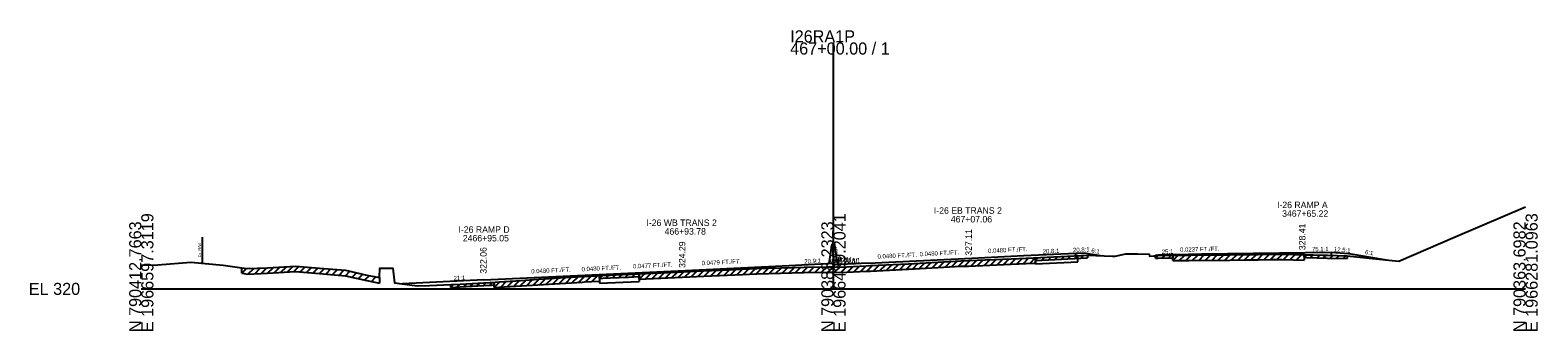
# Model space of a CAD drawing. Extents: x -44 to 4323, y -10 to 9601.
# Drawn here: x 3974.3 to 4322.8, y 5490.3 to 5559.8 of the extents above; entities that cross this region are included whole.
import ezdxf

# ---------------------------------------------------------------- set-up
doc = ezdxf.new("R2010")
doc.units = 0
for name, color, linetype in [('1', 7, 'Continuous'), ('DateStamp', 7, 'Continuous'), ('NotForConst', 7, 'Continuous'), ('QCQA', 7, 'Continuous'), ('RD_SHT_Bndy', 7, 'Continuous'), ('RD_SHT_Iplotshp', 7, 'Continuous'), ('RD_SHT_TX', 7, 'Continuous'), ('RD_XS_ExGround', 7, 'Continuous'), ('RD_XS_MedBWall', 7, 'Continuous'), ('RD_XS_Misc_Line', 7, 'Continuous'), ('RD_XS_Pave', 7, 'Continuous'), ('RD_XS_PaveOvlay', 7, 'Continuous'), ('RD_XS_PaveShd', 7, 'Continuous'), ('RD_XS_TX_Elev_PR', 7, 'Continuous'), ('RD_XS_TX_Profile', 7, 'Continuous'), ('RD_XS_TX_ShdSlope', 7, 'Continuous'), ('RD_XS_TX_Slope', 7, 'Continuous'), ('seal', 7, 'Continuous'), ('TR SN EXTRUDED PANEL SIGNS - GROUND MOUNTED', 7, 'Continuous')]:
    doc.layers.add(name, color=color, linetype=linetype)

msp = doc.modelspace()

# ---------------------------------------------------------------- linework, layer by layer
at = {"layer": 'DateStamp'}
msp.add_lwpolyline([(4000, 5505.47), (4003.81, 5505.6), (4011.45, 5506.18), (4018.89, 5505.45), (4023.21, 5504.85), (4023.8, 5504.83), (4024.5, 5504.69), (4029.18, 5504.89), (4035.64, 5505.24), (4041.22, 5504.83), (4047.17, 5504.3), (4052.17, 5503.21), (4055.03, 5502.6), (4055.14, 5504.79), (4056.24, 5504.79), (4058.14, 5504.79), (4058.5, 5501.43), (4063.27, 5500.78), (4063.83, 5500.68), (4066.62, 5500.79), (4071.55, 5500.98), (4073.68, 5501.11), (4080.54, 5501.49), (4080.98, 5501.51), (4082.67, 5501.63), (4086.58, 5501.89), (4093, 5502.3), (4101.98, 5502.84), (4102.47, 5502.87), (4106.72, 5503.1), (4108.39, 5503.18), (4112.59, 5503.38), (4115.05, 5503.49), (4118.43, 5503.64), (4130.06, 5504.16), (4138.96, 5504.58), (4142.28, 5504.73), (4153.23, 5505.02), (4158.57, 5505.13), (4160, 5505.09), (4161.33, 5505.04), (4163.09, 5505.12), (4167.58, 5505.32), (4168.59, 5505.37), (4177.35, 5505.79), (4186.84, 5506.32), (4189.47, 5506.47), (4191.22, 5506.54), (4201.11, 5506.95), (4206.35, 5507.2), (4218.7, 5507.8), (4224.5, 5507.57), (4225.14, 5507.53), (4227.61, 5508.11), (4230.33, 5508.09), (4232.97, 5508.03), (4233.07, 5507.58), (4234.13, 5507.67), (4234.44, 5507.7), (4235.06, 5507.71), (4238.44, 5507.79), (4242.25, 5507.82), (4251.6, 5507.88), (4255.59, 5507.93), (4258.18, 5507.97), (4261.19, 5508.02), (4263.67, 5508.05), (4266.35, 5507.98), (4269.33, 5507.91), (4274.21, 5507.77), (4278.79, 5507.64), (4283.86, 5507.14), (4290.68, 5506.42), (4303.75, 5512.04), (4320, 5518.99)], dxfattribs=at)
at = {"layer": 'NotForConst'}
for p, q in [((4197.85, 5505.56), (4199.15, 5506.87)), ((4199.35, 5505.63), (4200.66, 5506.93)), ((4200.85, 5505.69), (4202.17, 5507)), ((4202.36, 5505.76), (4203.68, 5507.07)), ((4203.86, 5505.83), (4205.18, 5507.15)), ((4205.37, 5505.9), (4206.69, 5507.22)), ((4206.7, 5506.59), (4207.36, 5507.25)), ((4208.21, 5506.67), (4208.86, 5507.32)), ((4209.71, 5506.74), (4210.37, 5507.4)), ((4211.21, 5506.81), (4211.87, 5507.47)), ((4212.72, 5506.88), (4213.38, 5507.54)), ((4214.22, 5506.96), (4214.88, 5507.61)), ((4215.73, 5507.03), (4216.39, 5507.69)), ((4217.23, 5507.1), (4217.89, 5507.76)), ((4234.44, 5507.07), (4235.08, 5507.71)), ((4235.95, 5507.1), (4236.59, 5507.74)), ((4237.45, 5507.14), (4238.09, 5507.78)), ((4238.44, 5506.54), (4239.7, 5507.8)), ((4239.95, 5506.55), (4241.21, 5507.81)), ((4241.45, 5506.56), (4242.71, 5507.82)), ((4242.96, 5506.57), (4244.22, 5507.83)), ((4244.46, 5506.58), (4245.72, 5507.84)), ((4245.97, 5506.59), (4247.23, 5507.85)), ((4247.47, 5506.6), (4248.73, 5507.86)), ((4248.97, 5506.61), (4250.24, 5507.87)), ((4250.48, 5506.62), (4251.74, 5507.88)), ((4251.98, 5506.63), (4253.26, 5507.9)), ((4253.49, 5506.65), (4254.76, 5507.92)), ((4254.99, 5506.68), (4256.27, 5507.94)), ((4256.5, 5506.7), (4257.77, 5507.97)), ((4258, 5506.72), (4259.28, 5507.99)), ((4259.51, 5506.74), (4260.78, 5508.01)), ((4261.01, 5506.76), (4262.28, 5508.03)), ((4262.52, 5506.78), (4263.78, 5508.05)), ((4264.02, 5506.79), (4265.25, 5508.01)), ((4265.53, 5506.75), (4266.75, 5507.97)), ((4267.03, 5506.72), (4268.26, 5507.94)), ((4268.79, 5507.3), (4269.4, 5507.91)), ((4270.29, 5507.26), (4270.9, 5507.86)), ((4271.79, 5507.21), (4272.4, 5507.82)), ((4273.3, 5507.17), (4273.91, 5507.78)), ((4274.8, 5507.13), (4275.41, 5507.73)), ((4276.31, 5507.08), (4276.92, 5507.69)), ((4277.81, 5507.04), (4278.42, 5507.65)), ((4023.21, 5503.6), (4024.33, 5504.72)), ((4024.71, 5503.45), (4026.01, 5504.75)), ((4026.21, 5503.51), (4027.51, 5504.82)), ((4027.71, 5503.58), (4029.01, 5504.89)), ((4029.21, 5503.65), (4030.53, 5504.97)), ((4030.71, 5503.73), (4032.03, 5505.05)), ((4032.21, 5503.81), (4033.53, 5505.13)), ((4033.71, 5503.89), (4035.03, 5505.21)), ((4035.21, 5503.97), (4036.42, 5505.18)), ((4036.71, 5503.91), (4037.87, 5505.08)), ((4038.21, 5503.8), (4039.37, 5504.97)), ((4039.71, 5503.69), (4040.87, 5504.86)), ((4041.21, 5503.58), (4042.35, 5504.73)), ((4042.71, 5503.45), (4043.85, 5504.6)), ((4044.21, 5503.31), (4045.35, 5504.46)), ((4045.71, 5503.18), (4046.85, 5504.32)), ((4047.21, 5503.04), (4048.23, 5504.06)), ((4048.71, 5502.71), (4049.73, 5503.74)), ((4050.21, 5502.39), (4051.23, 5503.41)), ((4111.94, 5502.72), (4112.6, 5503.38)), ((4113.44, 5502.79), (4114.1, 5503.44)), ((4115.08, 5502.24), (4116.39, 5503.55)), ((4116.58, 5502.31), (4117.9, 5503.61)), ((4118.09, 5502.37), (4119.4, 5503.68)), ((4119.59, 5502.44), (4120.91, 5503.75)), ((4121.1, 5502.51), (4122.41, 5503.82)), ((4122.6, 5502.58), (4123.92, 5503.89)), ((4124.11, 5502.64), (4125.42, 5503.95)), ((4125.61, 5502.71), (4126.93, 5504.02)), ((4127.12, 5502.78), (4128.43, 5504.09)), ((4128.62, 5502.85), (4129.94, 5504.16)), ((4130.13, 5502.92), (4131.44, 5504.23)), ((4131.63, 5502.99), (4132.95, 5504.3)), ((4133.14, 5503.06), (4134.45, 5504.37)), ((4134.64, 5503.13), (4135.96, 5504.44)), ((4136.15, 5503.2), (4137.46, 5504.51)), ((4137.65, 5503.27), (4138.97, 5504.58)), ((4139.16, 5503.34), (4140.47, 5504.65)), ((4140.66, 5503.41), (4141.98, 5504.72)), ((4142.17, 5503.48), (4143.46, 5504.76)), ((4143.67, 5503.52), (4144.96, 5504.8)), ((4145.18, 5503.56), (4146.46, 5504.84)), ((4146.68, 5503.6), (4147.97, 5504.88)), ((4148.18, 5503.63), (4149.47, 5504.92)), ((4149.69, 5503.67), (4150.98, 5504.96)), ((4151.19, 5503.71), (4152.48, 5505)), ((4152.7, 5503.75), (4153.98, 5505.03)), ((4154.2, 5503.79), (4155.49, 5505.06)), ((4155.71, 5503.82), (4156.99, 5505.1)), ((4157.21, 5503.85), (4158.5, 5505.13)), ((4158.72, 5503.87), (4159.94, 5505.09)), ((4160.22, 5503.83), (4161.45, 5505.05)), ((4161.73, 5503.81), (4163.04, 5505.12)), ((4163.23, 5503.88), (4164.55, 5505.19)), ((4164.74, 5503.95), (4166.05, 5505.25)), ((4166.24, 5504.01), (4167.56, 5505.32)), ((4167.75, 5504.08), (4169.07, 5505.39)), ((4169.25, 5504.15), (4170.57, 5505.47)), ((4170.76, 5504.22), (4172.08, 5505.54)), ((4172.26, 5504.3), (4173.58, 5505.61)), ((4173.77, 5504.37), (4175.09, 5505.68)), ((4175.27, 5504.44), (4176.59, 5505.76)), ((4176.78, 5504.52), (4178.1, 5505.83)), ((4178.28, 5504.59), (4179.61, 5505.92)), ((4179.79, 5504.68), (4181.11, 5506)), ((4181.29, 5504.76), (4182.62, 5506.09)), ((4182.8, 5504.85), (4184.12, 5506.17)), ((4184.3, 5504.93), (4185.63, 5506.25)), ((4185.81, 5505.01), (4187.13, 5506.34)), ((4187.31, 5505.1), (4188.64, 5506.42)), ((4188.82, 5505.18), (4190.14, 5506.5)), ((4190.32, 5505.25), (4191.63, 5506.56)), ((4191.83, 5505.32), (4193.13, 5506.62)), ((4193.33, 5505.38), (4194.64, 5506.68)), ((4194.84, 5505.44), (4196.14, 5506.75)), ((4196.34, 5505.5), (4197.65, 5506.81)), ((4051.71, 5502.06), (4052.74, 5503.09)), ((4053.21, 5501.74), (4054.24, 5502.77)), ((4071.55, 5500.36), (4072.21, 5501.02)), ((4073.05, 5500.44), (4073.72, 5501.11)), ((4074.56, 5500.53), (4075.22, 5501.19)), ((4076.06, 5500.62), (4076.73, 5501.28)), ((4077.57, 5500.7), (4078.23, 5501.36)), ((4079.07, 5500.79), (4079.74, 5501.45)), ((4080.58, 5500.87), (4081.24, 5501.53)), ((4081.58, 5500.3), (4082.92, 5501.65)), ((4083.08, 5500.41), (4084.43, 5501.75)), ((4084.59, 5500.51), (4085.93, 5501.85)), ((4086.09, 5500.61), (4087.44, 5501.94)), ((4087.6, 5500.71), (4088.94, 5502.04)), ((4089.1, 5500.8), (4090.44, 5502.14)), ((4090.61, 5500.9), (4091.95, 5502.24)), ((4092.11, 5501), (4093.45, 5502.33)), ((4093.62, 5501.09), (4094.95, 5502.42)), ((4095.12, 5501.18), (4096.46, 5502.51)), ((4096.63, 5501.27), (4097.96, 5502.6)), ((4098.13, 5501.36), (4099.47, 5502.69)), ((4099.64, 5501.45), (4100.97, 5502.78)), ((4101.14, 5501.54), (4102.47, 5502.87)), ((4102.65, 5501.63), (4103.97, 5502.95)), ((4104.15, 5501.71), (4105.48, 5503.03)), ((4105.92, 5502.43), (4106.58, 5503.09)), ((4107.42, 5502.51), (4108.08, 5503.16)), ((4108.93, 5502.58), (4109.59, 5503.23)), ((4110.43, 5502.65), (4111.09, 5503.3))]:
    msp.add_line(p, q, dxfattribs=at)
at = {"layer": 'QCQA'}
for p, q in [((4191.22, 5506.54), (4201.11, 5506.95)), ((4201.11, 5506.95), (4206.35, 5507.2)), ((4206.35, 5507.2), (4206.7, 5507.22)), ((4238.44, 5507.79), (4234.98, 5507.71)), ((4238.44, 5507.79), (4242.25, 5507.82)), ((4238.44, 5507.79), (4238.44, 5507.76)), ((4242.25, 5507.82), (4251.6, 5507.88)), ((4251.6, 5507.88), (4255.59, 5507.93)), ((4255.59, 5507.93), (4258.18, 5507.97)), ((4258.18, 5507.97), (4261.19, 5508.02)), ((4261.19, 5508.02), (4263.67, 5508.05)), ((4263.67, 5508.05), (4266.35, 5507.98)), ((4266.35, 5507.98), (4268.79, 5507.92)), ((4268.79, 5507.92), (4275.13, 5507.74)), ((4105.92, 5503.06), (4115.08, 5503.49)), ((4115.08, 5503.49), (4118.43, 5503.64)), ((4115.08, 5503.49), (4115.08, 5501.74)), ((4118.43, 5503.64), (4130.06, 5504.16)), ((4130.06, 5504.16), (4138.96, 5504.58)), ((4138.96, 5504.58), (4142.28, 5504.73)), ((4142.28, 5504.73), (4153.23, 5505.02)), ((4153.23, 5505.02), (4158.57, 5505.13)), ((4158.57, 5505.13), (4160, 5505.09)), ((4160, 5505.09), (4161.33, 5505.04)), ((4161.33, 5505.04), (4163.09, 5505.12)), ((4163.09, 5505.12), (4167.58, 5505.32)), ((4167.58, 5505.32), (4168.59, 5505.37)), ((4168.59, 5505.37), (4177.35, 5505.79)), ((4177.35, 5505.79), (4186.84, 5506.32)), ((4186.84, 5506.32), (4189.47, 5506.47)), ((4189.47, 5506.47), (4191.22, 5506.54)), ((4105.92, 5503.06), (4105.92, 5501.3))]:
    msp.add_line(p, q, dxfattribs=at)
at = {"layer": 'RD_SHT_Bndy'}
for p, q in [((4160, 5500), (4160, 5556.96)), ((4000, 5500), (4160, 5500)), ((4160, 5500), (4320, 5500))]:
    msp.add_line(p, q, dxfattribs=at)
at = {"layer": 'RD_SHT_Iplotshp'}
for p, q in [((4206.7, 5507.22), (4206.7, 5505.97)), ((4206.7, 5506.59), (4206.7, 5507.22)), ((4206.7, 5506.59), (4218.7, 5507.17)), ((4218.7, 5507.8), (4218.7, 5507.17)), ((4234.44, 5507.07), (4234.44, 5507.7)), ((4234.44, 5507.07), (4235.06, 5507.08)), ((4235.06, 5507.08), (4238.44, 5507.16)), ((4238.44, 5506.54), (4238.44, 5507.79)), ((4238.44, 5507.79), (4238.44, 5507.16)), ((4238.44, 5507.16), (4238.44, 5507.16)), ((4268.79, 5507.92), (4268.79, 5506.67)), ((4268.79, 5507.3), (4268.79, 5507.92)), ((4268.79, 5507.3), (4269.33, 5507.29)), ((4269.33, 5507.29), (4274.21, 5507.14)), ((4274.21, 5507.14), (4278.79, 5507.02)), ((4278.79, 5507.64), (4278.79, 5507.02)), ((4023.21, 5503.6), (4023.21, 5504.85)), ((4023.21, 5503.6), (4023.8, 5503.58)), ((4023.8, 5503.58), (4024.5, 5503.44)), ((4024.5, 5503.44), (4029.18, 5503.64)), ((4029.18, 5503.64), (4035.64, 5503.99)), ((4035.64, 5503.99), (4041.22, 5503.58)), ((4041.22, 5503.58), (4047.17, 5503.05)), ((4115.08, 5502.24), (4115.08, 5503.49)), ((4115.08, 5503.49), (4115.08, 5502.86)), ((4138.96, 5503.33), (4142.28, 5503.48)), ((4142.28, 5503.48), (4153.23, 5503.77)), ((4153.23, 5503.77), (4158.57, 5503.88)), ((4158.57, 5503.88), (4160, 5503.84)), ((4160, 5503.84), (4161.33, 5503.79)), ((4161.33, 5503.79), (4163.09, 5503.87)), ((4163.09, 5503.87), (4167.58, 5504.07)), ((4167.58, 5504.07), (4168.59, 5504.12)), ((4168.59, 5504.12), (4177.35, 5504.54)), ((4177.35, 5504.54), (4186.84, 5505.07)), ((4186.84, 5505.07), (4189.47, 5505.22)), ((4189.47, 5505.22), (4191.22, 5505.29)), ((4191.22, 5505.29), (4201.11, 5505.7)), ((4201.11, 5505.7), (4206.35, 5505.95)), ((4206.35, 5505.95), (4206.7, 5505.97)), ((4238.44, 5506.54), (4242.25, 5506.57)), ((4242.25, 5506.57), (4251.6, 5506.63)), ((4251.6, 5506.63), (4255.59, 5506.68)), ((4255.59, 5506.68), (4258.18, 5506.72)), ((4258.18, 5506.72), (4261.19, 5506.77)), ((4261.19, 5506.77), (4263.67, 5506.8)), ((4263.67, 5506.8), (4266.35, 5506.73)), ((4266.35, 5506.73), (4268.79, 5506.67)), ((4047.17, 5503.05), (4052.17, 5501.96)), ((4052.17, 5501.96), (4055.03, 5501.35)), ((4055.03, 5502.6), (4055.03, 5501.35)), ((4071.55, 5500.36), (4071.55, 5500.98)), ((4071.55, 5500.36), (4073.68, 5500.48)), ((4073.68, 5500.48), (4080.54, 5500.87)), ((4080.54, 5500.87), (4080.98, 5500.89)), ((4080.98, 5500.89), (4081.58, 5500.93)), ((4081.58, 5500.3), (4081.58, 5501.55)), ((4081.58, 5501.55), (4081.58, 5500.93)), ((4081.58, 5500.3), (4082.67, 5500.38)), ((4082.67, 5500.38), (4086.58, 5500.64)), ((4086.58, 5500.64), (4093, 5501.05)), ((4093, 5501.05), (4101.98, 5501.59)), ((4101.98, 5501.59), (4102.47, 5501.62)), ((4102.47, 5501.62), (4105.92, 5501.81)), ((4105.92, 5503.06), (4105.92, 5501.81)), ((4105.92, 5502.43), (4105.92, 5503.06)), ((4105.92, 5502.43), (4106.72, 5502.48)), ((4106.72, 5502.48), (4108.39, 5502.55)), ((4108.39, 5502.55), (4112.59, 5502.75)), ((4112.59, 5502.75), (4115.05, 5502.86)), ((4115.05, 5502.86), (4115.08, 5502.86)), ((4115.08, 5502.24), (4118.43, 5502.39)), ((4118.43, 5502.39), (4130.06, 5502.91)), ((4130.06, 5502.91), (4138.96, 5503.33))]:
    msp.add_line(p, q, dxfattribs=at)
at = {"layer": 'RD_XS_Misc_Line'}
for p, q in [((4206.7, 5505.78), (4206.7, 5507.22)), ((4216, 5507.7), (4216, 5508.26)), ((4216, 5507.7), (4216.5, 5507.73)), ((4216.5, 5506.25), (4216.5, 5507.73)), ((4234.98, 5507.71), (4234.98, 5507.78)), ((4275.13, 5507.74), (4275.13, 5508.49)), ((4206.7, 5505.78), (4216.5, 5506.25)), ((4105.92, 5501.3), (4115.08, 5501.74))]:
    msp.add_line(p, q, dxfattribs=at)
at = {"layer": 'RD_XS_Pave'}
for p, q in [((4218, 5508.36), (4222.21, 5507.66)), ((4279.13, 5508.17), (4287.77, 5506.73))]:
    msp.add_line(p, q, dxfattribs=at)
at = {"layer": 'RD_XS_PaveOvlay'}
msp.add_line((4014.08, 5511.92), (4014.08, 5505.92), dxfattribs=at)
at = {"layer": 'RD_XS_PaveShd'}
for p, q in [((4216, 5508.26), (4218, 5508.36)), ((4234.98, 5507.78), (4234.44, 5507.7)), ((4275.13, 5508.49), (4279.13, 5508.17))]:
    msp.add_line(p, q, dxfattribs=at)
at = {"layer": 'RD_XS_TX_Elev_PR'}
for p, q in [((4204, 5507.69), (4216, 5508.26)), ((4238.98, 5507.94), (4234.98, 5507.78)), ((4269.12, 5508.41), (4275.13, 5508.49)), ((4149.78, 5505.44), (4160, 5505.93)), ((4168, 5505.96), (4160, 5505.57)), ((4160, 5505.93), (4160, 5505.57)), ((4079.22, 5502.06), (4060.42, 5501.17))]:
    msp.add_line(p, q, dxfattribs=at)
at = {"layer": 'RD_XS_TX_ShdSlope'}
for p, q in [((4159, 5505.88), (4159.67, 5510.43)), ((4160.33, 5510.43), (4159.67, 5510.43)), ((4160, 5510.43), (4159.67, 5510.43)), ((4160.33, 5510.07), (4160.33, 5510.43)), ((4161, 5505.62), (4160.33, 5510.07))]:
    msp.add_line(p, q, dxfattribs=at)
at = {"layer": 'RD_XS_TX_Slope'}
for p, q in [((4168, 5505.96), (4192, 5507.11)), ((4192, 5507.11), (4204, 5507.69)), ((4238.98, 5507.94), (4245.07, 5508.09)), ((4245.07, 5508.09), (4269.12, 5508.41)), ((4079.22, 5502.06), (4125.78, 5504.29)), ((4125.78, 5504.29), (4149.78, 5505.44))]:
    msp.add_line(p, q, dxfattribs=at)

# ---------------------------------------------------------------- texts
at = {"layer": '1'}
for s, p in [('I-26 EB TRANS 2', (4183.22, 5517.36)), ('I-26 RAMP A', (4262.55, 5518.66)), ('3467+65.22', (4263.73, 5516.66)), ('I-26 RAMP D', (4073.33, 5512.97)), ('I-26 WB TRANS 2', (4116.77, 5514.54)), ('466+93.78', (4120.98, 5512.54)), ('467+07.06', (4187.14, 5515.36)), ('2466+95.05', (4074.33, 5510.97))]:
    msp.add_text(s, height=1.5, dxfattribs=at).set_placement(p)
at = {"layer": 'RD_SHT_Bndy'}
for s, p in [('I26RA1P', (4150, 5556.96)), ('467+00.00 / 1', (4150, 5554.16)), ('EL 320', (3974, 5498.6))]:
    msp.add_text(s, height=2.8, dxfattribs=at).set_placement(p)
for s, p in [('E 1966597.3119', (4002.8, 5490)), ('E 1966439.2041', (4162.8, 5490)), ('E 1966281.0963', (4322.8, 5490)), ('N 790412.7663', (4000, 5490)), ('N 790388.2323', (4160, 5490)), ('N 790363.6982', (4320, 5490))]:
    msp.add_text(s, height=2.8, rotation=90, dxfattribs=at).set_placement(p)
at = {"layer": 'RD_SHT_TX'}
msp.add_text('325.09', height=1, rotation=90, dxfattribs=at).set_placement((4161, 5505.09))
at = {"layer": 'RD_XS_ExGround'}
for s, rotation, p in [('20.9:1', 2.7412, (4153.3, 5505.86)), ('20.8:1', 2.7481, (4162.41, 5505.94)), ('20.8:1', 2.7481, (4208.41, 5508.15)), ('21:1', 2.7314, (4072.22, 5501.98))]:
    msp.add_text(s, height=1, rotation=rotation, dxfattribs=at).set_placement(p)
at = {"layer": 'RD_XS_MedBWall'}
for s, rotation, p in [('20.8:1', 2.7481, (4215.41, 5508.48)), ('12.5:1', 355.4301, (4275.67, 5508.69))]:
    msp.add_text(s, height=1, rotation=rotation, dxfattribs=at).set_placement(p)
at = {"layer": 'RD_XS_PaveOvlay'}
msp.add_text('Ex. R/W ', height=0.65, rotation=90, dxfattribs=at).set_placement((4013.83, 5507.31))
at = {"layer": 'RD_XS_TX_Profile'}
for s, p in [('WBW', (4159, 5505.88)), ('EBW', (4161, 5505.62))]:
    msp.add_text(s, height=1.5, dxfattribs=at).set_placement(p)
at = {"layer": 'seal'}
for s, p in [(' 328.41', (4269.12, 5508.41)), (' 324.29', (4125.78, 5504.29)), (' 327.11', (4192, 5507.11)), ('322.06', (4079.83, 5503.52))]:
    msp.add_text(s, height=1.5, rotation=90, dxfattribs=at).set_placement(p)
at = {"layer": 'TR SN EXTRUDED PANEL SIGNS - GROUND MOUNTED'}
for s, rotation, p in [('0.0479 FT./FT.', 2.7412, (4129.55, 5505.47)), ('0.0480 FT./FT.', 2.7481, (4170.22, 5506.98)), ('0.0480 FT./FT.', 2.7481, (4179.95, 5507.53)), ('0.0480 FT./FT.', 2.7481, (4195.77, 5508.29)), ('6:1', 350.5377, (4219.57, 5508.44)), ('25:1', 2.2899, (4235.92, 5508.07)), ('0.0237 FT./FT.', 1.357, (4240.14, 5508.57)), ('75.1:1', 0.7628, (4270.64, 5508.68)), ('6:1', 350.546, (4282.84, 5508.06)), ('0.0480 FT./FT.', 2.75, (4090.17, 5503.56)), ('0.0480 FT./FT.', 2.7458, (4101.8, 5504.05)), ('0.0477 FT./FT.', 2.7314, (4113.69, 5504.72))]:
    msp.add_text(s, height=1, rotation=rotation, dxfattribs=at).set_placement(p)

doc.saveas('drawing.dxf')
